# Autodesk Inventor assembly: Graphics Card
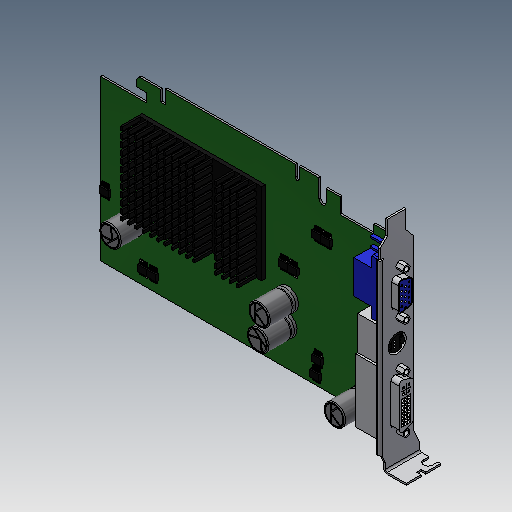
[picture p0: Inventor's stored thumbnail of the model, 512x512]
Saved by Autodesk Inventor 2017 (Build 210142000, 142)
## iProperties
Created: 2005-12
Part Number: Graphics Card
Document SubType Name: Assembly
Designer: DanielSeverino
Author: DanielSeverino
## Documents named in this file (7)
- C:\Users\DanielSeverino\Desktop\01\Graphics Card.iam
- C:\Users\DanielSeverino\Desktop\01\Graphic Card PCB.ipt
- C:\Users\DanielSeverino\Desktop\01\Capacitor 3500 UF.ipt
- C:\Users\DanielSeverino\Desktop\01\Graphic Card Heat Sink.ipt
- C:\Users\DanielSeverino\Desktop\01\Chip 5 x 3.ipt
- C:\Users\DanielSeverino\Desktop\01\Chip 22 x 11.ipt
- C:\Users\DanielSeverino\Desktop\01\Graphic Card Sheetmetal.ipt
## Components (18 placed, 6 different names)
1. Graphic Card PCB:1
2. Capacitor 3500 UF:1
3. Capacitor 3500 UF:2
4. Capacitor 3500 UF:3
5. Graphic Card Heat Sink:1
6. Capacitor 3500 UF:4
7. Chip 5 x 3:1
8. Chip 5 x 3:2
9. Chip 5 x 3:3
10. Chip 5 x 3:4
11. Chip 5 x 3:5
12. Chip 22 x 11:1
13. Chip 22 x 11:2
14. Chip 5 x 3:6
15. Chip 5 x 3:7
16. Chip 5 x 3:8
17. Chip 5 x 3:9
18. Graphic Card Sheetmetal:1
